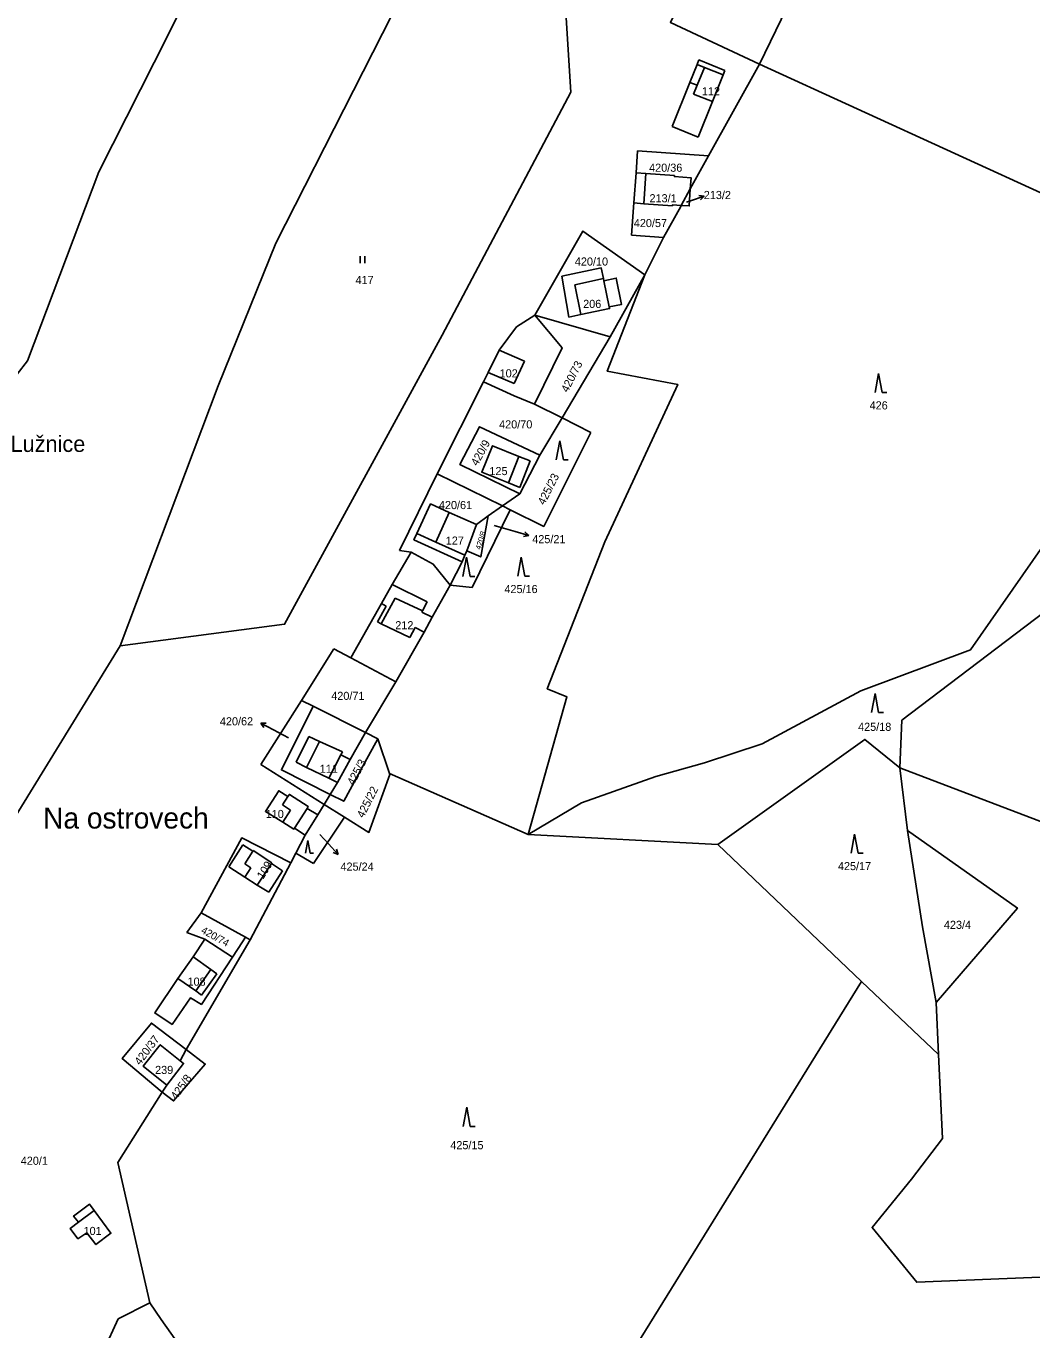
# Model space of a CAD drawing. Extents: x -7483133 to -743907, y -11317770 to -1129777.
# Drawn here: x -748843.6 to -748633, y -1130396.9 to -1130123.8 of the extents above; entities that cross this region are included whole.
import ezdxf

# ---------------------------------------------------------------- set-up
doc = ezdxf.new("R2010")
doc.units = 0
for name, color, linetype in [('Hranice parcel', 7, 'Continuous'), ('Parcelní čísla', 7, 'Continuous'), ('Pop  PČ popisy', 7, 'Continuous'), ('Vnitřní kresba', 7, 'Continuous'), ('Značky kultur', 7, 'Continuous')]:
    doc.layers.add(name, color=color, linetype=linetype)

msp = doc.modelspace()

# ---------------------------------------------------------------- linework, layer by layer
at = {"layer": 'Hranice parcel'}
for p, q in [((-748679.01, -1130109.09), (-748690.03, -1130131.77)), ((-748697.25, -1130133.11), (-748702.73, -1130130.9)), ((-748700.69, -1130150.98), (-748690.03, -1130131.77)), ((-748708.33, -1130144.85), (-748702.84, -1130147.05)), ((-748704.51, -1130157.91), (-748700.69, -1130150.98)), ((-748716.32, -1130160.85), (-748715.86, -1130154.54)), ((-748706.41, -1130161.37), (-748704.51, -1130157.91)), ((-748714, -1130175.92), (-748710.11, -1130168.08)), ((-748721.25, -1130188.87), (-748714, -1130175.92)), ((-748737.09, -1130184.36), (-748721.25, -1130188.87)), ((-748721.25, -1130188.87), (-748731.36, -1130205.88)), ((-748757.48, -1130217.6), (-748747.82, -1130198.29)), ((-748731.36, -1130205.88), (-748737.1, -1130203.01)), ((-748735.98, -1130213.67), (-748731.36, -1130205.88)), ((-748731.36, -1130205.88), (-748725.34, -1130208.89)), ((-748740.17, -1130221.76), (-748735.98, -1130213.67)), ((-748740.23, -1130220.41), (-748738.01, -1130214.88)), ((-748765.43, -1130233.66), (-748757.48, -1130217.6)), ((-748743.82, -1130224.3), (-748757.48, -1130217.6)), ((-748743.82, -1130224.3), (-748740.17, -1130221.76)), ((-748746.82, -1130226.39), (-748743.82, -1130224.3)), ((-748742.19, -1130225.1), (-748743.82, -1130224.3)), ((-748742.19, -1130225.1), (-748750.19, -1130241.4)), ((-748746.82, -1130226.39), (-748749.28, -1130228.17)), ((-748751.33, -1130233.71), (-748749.28, -1130228.17)), ((-748762.98, -1130234.01), (-748765.43, -1130233.66)), ((-748754.82, -1130240.9), (-748752.26, -1130236.01)), ((-748750.19, -1130241.4), (-748754.82, -1130240.9)), ((-748785.95, -1130265.03), (-748779.14, -1130254.21)), ((-748779.14, -1130254.21), (-748775.58, -1130256.1)), ((-748775.58, -1130256.1), (-748766.14, -1130261.11)), ((-748766.14, -1130261.11), (-748772.5, -1130271.71)), ((-748794.41, -1130278.46), (-748785.95, -1130265.03)), ((-748783.49, -1130266.25), (-748785.95, -1130265.03)), ((-748772.5, -1130271.71), (-748783.49, -1130266.25)), ((-748769.96, -1130273.07), (-748772.5, -1130271.71)), ((-748769.96, -1130273.07), (-748767.48, -1130280.32)), ((-748781.17, -1130286.79), (-748794.41, -1130278.46)), ((-748660.62, -1130279.14), (-748659.01, -1130292.27)), ((-748738.44, -1130293.13), (-748767.48, -1130280.32)), ((-748767.48, -1130280.32), (-748767.41, -1130280.54)), ((-748781.17, -1130286.79), (-748779.93, -1130284.72)), ((-748782.51, -1130289.02), (-748781.17, -1130286.79)), ((-748781.17, -1130286.79), (-748776.93, -1130289.46)), ((-748785.13, -1130293.23), (-748782.51, -1130289.02)), ((-748776.93, -1130289.46), (-748783.4, -1130299.2)), ((-748787.12, -1130297.03), (-748785.13, -1130293.23)), ((-748698.75, -1130295.21), (-748738.44, -1130293.13)), ((-748668.63, -1130323.88), (-748698.75, -1130295.21)), ((-748788.18, -1130299.06), (-748787.12, -1130297.03)), ((-748783.4, -1130299.2), (-748787.12, -1130297.03)), ((-748796.64, -1130315.17), (-748788.18, -1130299.06)), ((-748809.94, -1130313.62), (-748806.96, -1130309.5)), ((-748806.96, -1130309.5), (-748797.65, -1130314.62)), ((-748806.14, -1130315.03), (-748809.94, -1130313.62)), ((-748800.38, -1130318.82), (-748806.14, -1130315.03)), ((-748797.65, -1130314.62), (-748796.64, -1130315.17)), ((-748810.09, -1130338.15), (-748796.64, -1130315.17)), ((-748652.52, -1130339.21), (-748668.63, -1130323.88)), ((-748653.04, -1130328.3), (-748652.52, -1130339.21)), ((-748811.31, -1130340.5), (-748810.09, -1130338.15)), ((-748815.11, -1130347.07), (-748814.15, -1130345.6))]:
    msp.add_line(p, q, dxfattribs=at)
for points in [[(-748769.65, -1130027.77), (-748783.5, -1130064.22), (-748813.85, -1130125.61), (-748828.39, -1130154.34), (-748843.29, -1130193.93), (-748849.85, -1130202.28), (-748880.72, -1130244.6), (-748895.14, -1130258.31), (-748902.53, -1130266.04), (-748946.04, -1130295.61), (-748968.51, -1130326.73), (-748986.86, -1130352.14), (-749004.75, -1130374.8), (-749024.24, -1130390.9), (-749046.5, -1130403.57), (-749076.25, -1130410.73)], [(-748690.03, -1130131.77), (-748708.67, -1130123.04), (-748703.2, -1130111.36), (-748695.73, -1130100.54)], [(-748758.78, -1130105.24), (-748791.3, -1130169.26), (-748803.39, -1130199.17), (-748823.92, -1130253.6)], [(-748823.92, -1130253.6), (-748789.46, -1130249.07), (-748756.47, -1130188.54), (-748729.51, -1130137.61), (-748730.72, -1130118.71)], [(-748702.73, -1130130.9), (-748703.1, -1130131.83), (-748704.61, -1130135.59), (-748708.33, -1130144.85)], [(-748690.03, -1130131.77), (-748628.64, -1130159.81), (-748623.71, -1130149.3)], [(-748702.84, -1130147.05), (-748699.88, -1130139.6), (-748697.62, -1130134.04), (-748697.25, -1130133.11)], [(-748715.86, -1130154.54), (-748715.53, -1130149.95), (-748700.69, -1130150.98)], [(-748715.86, -1130154.54), (-748713.83, -1130154.69), (-748707.83, -1130155.12), (-748707.84, -1130155.32), (-748704.35, -1130155.56), (-748704.51, -1130157.91)], [(-748704.51, -1130157.91), (-748704.74, -1130161.48), (-748706.41, -1130161.37)], [(-748710.11, -1130168.08), (-748716.81, -1130167.59), (-748716.32, -1130160.85)], [(-748706.41, -1130161.37), (-748708.24, -1130161.24), (-748708.25, -1130161.44), (-748714.25, -1130161), (-748716.32, -1130160.85)], [(-748710.11, -1130168.08), (-748706.52, -1130161.56), (-748706.41, -1130161.37)], [(-748737.09, -1130184.36), (-748726.98, -1130166.73), (-748714, -1130175.92)], [(-748731.39, -1130176.15), (-748729.92, -1130184.74), (-748727.41, -1130184.22), (-748721.4, -1130182.98), (-748721.47, -1130182.61), (-748718.88, -1130182.08), (-748720.01, -1130176.57), (-748722.61, -1130177.15), (-748722.7, -1130176.69), (-748723.16, -1130174.45), (-748731.39, -1130176.15)], [(-748738.44, -1130293.13), (-748730.34, -1130264.28), (-748734.46, -1130262.58), (-748722.39, -1130231.8), (-748707.13, -1130198.83), (-748721.89, -1130196.08), (-748714, -1130175.92)], [(-748737.09, -1130184.36), (-748740.9, -1130186.8), (-748744.52, -1130191.64), (-748746.84, -1130196.34), (-748747.82, -1130198.29)], [(-748737.1, -1130203.01), (-748731.34, -1130191.16), (-748737.09, -1130184.36)], [(-748747.82, -1130198.29), (-748741.36, -1130201.22), (-748737.1, -1130203.01)], [(-748735.98, -1130213.67), (-748748.65, -1130207.73), (-748752.73, -1130215.64), (-748740.17, -1130221.76)], [(-748725.34, -1130208.89), (-748735.2, -1130228.6), (-748742.19, -1130225.1)], [(-748738.01, -1130214.88), (-748740.38, -1130213.93), (-748745.94, -1130211.69), (-748748.16, -1130217.21), (-748742.6, -1130219.46), (-748740.23, -1130220.41)], [(-748749.28, -1130228.17), (-748754.98, -1130225.64), (-748758.89, -1130223.86), (-748761.74, -1130230.08), (-748762.39, -1130231.38), (-748752.26, -1130236.01)], [(-748751.33, -1130233.71), (-748748.4, -1130234.96), (-748746.82, -1130226.39)], [(-748619.86, -1130238.05), (-748630.7, -1130232.75), (-748645.83, -1130254.45), (-748668.82, -1130263), (-748689.45, -1130274.13), (-748701.54, -1130278.1), (-748711.73, -1130280.94), (-748727.3, -1130286.44), (-748738.44, -1130293.13)], [(-748762.98, -1130234.01), (-748766.91, -1130240.77), (-748769.14, -1130244.76), (-748775.58, -1130256.1)], [(-748754.82, -1130240.9), (-748758.32, -1130236.48), (-748762.98, -1130234.01)], [(-748752.26, -1130236.01), (-748751.69, -1130234.6), (-748751.33, -1130233.71)], [(-748766.14, -1130261.11), (-748760.24, -1130250.76), (-748758.55, -1130247.6), (-748754.82, -1130240.9)], [(-748602.94, -1130272.05), (-748603.83, -1130270.75), (-748594.68, -1130253.65), (-748610.6, -1130247.49), (-748624.3, -1130241.91), (-748660.24, -1130269.18), (-748660.62, -1130279.14)], [(-748823.92, -1130253.6), (-748854.96, -1130304.08), (-748855.51, -1130336.17), (-748864.43, -1130348.37)], [(-748783.49, -1130266.25), (-748790.13, -1130279.57), (-748779.93, -1130284.72)], [(-748779.93, -1130284.72), (-748778.37, -1130282.24), (-748775.74, -1130277.43), (-748772.5, -1130271.71)], [(-748779.93, -1130284.72), (-748777.08, -1130286.16), (-748772.66, -1130278.04), (-748769.96, -1130273.07)], [(-748660.62, -1130279.14), (-748667.98, -1130273.2), (-748698.75, -1130295.21)], [(-748599.78, -1130276.68), (-748625.99, -1130292.35), (-748660.62, -1130279.14)], [(-748767.41, -1130280.54), (-748771.8, -1130292.68), (-748776.93, -1130289.46)], [(-748782.51, -1130289.02), (-748784.73, -1130287.64), (-748784.5, -1130287.26), (-748788.46, -1130284.72), (-748788.75, -1130285.18), (-748790.68, -1130283.93), (-748793.48, -1130288.27), (-748789.82, -1130290.55), (-748787.52, -1130291.98), (-748787.42, -1130291.81), (-748785.13, -1130293.23)], [(-748659.01, -1130292.27), (-748635.99, -1130308.5), (-748653.04, -1130328.3)], [(-748659.01, -1130292.27), (-748655.88, -1130312.42), (-748653.04, -1130328.3)], [(-748788.18, -1130299.06), (-748798.43, -1130293.81), (-748806.96, -1130309.5)], [(-748806.14, -1130315.03), (-748808.63, -1130318.75), (-748811.81, -1130323.23), (-748816.64, -1130330.48), (-748813.01, -1130332.88), (-748809.18, -1130327.32), (-748806.88, -1130328.7), (-748800.38, -1130318.82)], [(-748797.65, -1130314.62), (-748798.26, -1130315.56), (-748800.38, -1130318.82)], [(-748668.63, -1130323.88), (-748723.49, -1130412.55), (-748757.6, -1130467.05)], [(-748815.11, -1130347.07), (-748823.47, -1130340.04), (-748817.34, -1130332.61), (-748810.09, -1130338.15)], [(-748811.31, -1130340.5), (-748815.51, -1130337.13), (-748819.07, -1130341.63), (-748814.15, -1130345.6)], [(-748815.11, -1130347.07), (-748812.71, -1130348.9), (-748806.07, -1130341.2), (-748810.09, -1130338.15)], [(-748652.52, -1130339.21), (-748651.69, -1130356.8), (-748658.21, -1130365.26), (-748666.43, -1130375.43), (-748657.09, -1130386.87), (-748627.84, -1130385.7), (-748608.98, -1130393.62)], [(-748814.15, -1130345.6), (-748810.6, -1130341.06), (-748811.31, -1130340.5)], [(-748817.71, -1130391.16), (-748824.37, -1130361.8), (-748815.11, -1130347.07)], [(-748830.87, -1130376.52), (-748828.98, -1130378.98), (-748825.82, -1130376.61), (-748829.31, -1130371.87), (-748830.3, -1130370.53), (-748833.64, -1130373.02), (-748832.62, -1130374.32), (-748834.33, -1130375.61), (-748832.74, -1130377.75), (-748830.87, -1130376.52)], [(-748825.64, -1130435.7), (-748830.6, -1130413.85), (-748827.29, -1130401.09), (-748824.29, -1130394.55), (-748817.71, -1130391.16)], [(-748804.37, -1130410.14), (-748815.28, -1130394.69), (-748817.71, -1130391.16)]]:
    msp.add_lwpolyline(points, dxfattribs=at)
at = {"layer": 'Pop  PČ popisy'}
for p, q in [((-748704.43, -1130160.38), (-748701.59, -1130159.4)), ((-748701.59, -1130159.4), (-748702.7, -1130159.26)), ((-748701.59, -1130159.4), (-748702.38, -1130160.2)), ((-748705.32, -1130160.69), (-748704.43, -1130160.38)), ((-748745.61, -1130228.38), (-748741.21, -1130229.65)), ((-748741.21, -1130229.65), (-748738.33, -1130230.48)), ((-748738.33, -1130230.48), (-748739.43, -1130230.68)), ((-748738.33, -1130230.48), (-748739.15, -1130229.72)), ((-748791.8, -1130271.18), (-748794.45, -1130269.77)), ((-748794.45, -1130269.77), (-748793.33, -1130269.8)), ((-748794.45, -1130269.77), (-748793.8, -1130270.68)), ((-748788.66, -1130272.87), (-748791.8, -1130271.18)), ((-748782.11, -1130293.1), (-748780.3, -1130295.07)), ((-748780.3, -1130295.07), (-748778.25, -1130297.27)), ((-748778.25, -1130297.27), (-748779.3, -1130296.87)), ((-748778.25, -1130297.27), (-748778.57, -1130296.19))]:
    msp.add_line(p, q, dxfattribs=at)
at = {"layer": 'Vnitřní kresba'}
for p, q in [((-748701.56, -1130132.45), (-748703.1, -1130131.83)), ((-748701.56, -1130132.45), (-748703.07, -1130136.19)), ((-748697.62, -1130134.04), (-748701.56, -1130132.45)), ((-748703.07, -1130136.19), (-748704.61, -1130135.59)), ((-748703.81, -1130138.03), (-748703.07, -1130136.19)), ((-748699.88, -1130139.6), (-748703.81, -1130138.03)), ((-748713.83, -1130154.69), (-748714.25, -1130161)), ((-748728.7, -1130178), (-748722.7, -1130176.69)), ((-748728.7, -1130178), (-748727.41, -1130184.22)), ((-748722.61, -1130177.15), (-748721.47, -1130182.61)), ((-748744.52, -1130191.64), (-748739.2, -1130193.97)), ((-748739.2, -1130193.97), (-748741.36, -1130198.67)), ((-748741.36, -1130198.67), (-748746.84, -1130196.34)), ((-748740.38, -1130213.93), (-748742.6, -1130219.46)), ((-748754.98, -1130225.64), (-748757.76, -1130231.87)), ((-748761.74, -1130230.08), (-748757.76, -1130231.87)), ((-748757.76, -1130231.87), (-748751.69, -1130234.6)), ((-748766.91, -1130240.77), (-748759.59, -1130244.35)), ((-748769.23, -1130249), (-748766.3, -1130243.62)), ((-748760.57, -1130246.28), (-748766.3, -1130243.62)), ((-748769.98, -1130248.6), (-748768.19, -1130245.29)), ((-748768.19, -1130245.29), (-748769.14, -1130244.76)), ((-748760.57, -1130246.28), (-748760.7, -1130246.53)), ((-748760.7, -1130246.53), (-748758.55, -1130247.6)), ((-748759.59, -1130244.35), (-748760.57, -1130246.28)), ((-748769.23, -1130249), (-748769.98, -1130248.6)), ((-748769.23, -1130249), (-748763.24, -1130251.82)), ((-748763.24, -1130251.82), (-748762.13, -1130249.77)), ((-748762.13, -1130249.77), (-748760.24, -1130250.76)), ((-748784.36, -1130272.57), (-748787.03, -1130277.99)), ((-748782.13, -1130273.6), (-748784.84, -1130279.06)), ((-748784.36, -1130272.57), (-748782.13, -1130273.6)), ((-748782.13, -1130273.6), (-748777.35, -1130275.8)), ((-748777.66, -1130276.43), (-748780.2, -1130281.31)), ((-748777.35, -1130275.8), (-748777.66, -1130276.43)), ((-748777.66, -1130276.43), (-748775.74, -1130277.43)), ((-748787.03, -1130277.99), (-748784.84, -1130279.06)), ((-748784.84, -1130279.06), (-748780.2, -1130281.31)), ((-748780.2, -1130281.31), (-748778.37, -1130282.24)), ((-748789.9, -1130286.91), (-748788.75, -1130285.18)), ((-748788.2, -1130288.01), (-748789.9, -1130286.91)), ((-748784.73, -1130287.64), (-748787.42, -1130291.81)), ((-748788.2, -1130288.01), (-748789.82, -1130290.55)), ((-748801.13, -1130299.89), (-748798.19, -1130295.26)), ((-748798.19, -1130295.26), (-748796.14, -1130296.6)), ((-748797.81, -1130299.24), (-748796.14, -1130296.6)), ((-748796.14, -1130296.6), (-748796.06, -1130296.47)), ((-748796.06, -1130296.47), (-748792.1, -1130299.05)), ((-748801.13, -1130299.89), (-748797.8, -1130302.06)), ((-748796.51, -1130300.08), (-748797.81, -1130299.24)), ((-748796.51, -1130300.08), (-748797.8, -1130302.06)), ((-748792.21, -1130299.21), (-748795.2, -1130303.75)), ((-748789.87, -1130300.75), (-748792.77, -1130305.21)), ((-748792.1, -1130299.05), (-748792.21, -1130299.21)), ((-748792.21, -1130299.21), (-748789.87, -1130300.75)), ((-748797.8, -1130302.06), (-748795.2, -1130303.75)), ((-748792.77, -1130305.21), (-748795.2, -1130303.75)), ((-748808.63, -1130318.75), (-748804.89, -1130321.4)), ((-748808.08, -1130325.85), (-748811.81, -1130323.23)), ((-748804.89, -1130321.4), (-748808.08, -1130325.85)), ((-748803.64, -1130322.29), (-748806.86, -1130326.76)), ((-748804.89, -1130321.4), (-748803.64, -1130322.29)), ((-748806.86, -1130326.76), (-748808.08, -1130325.85)), ((-748832.62, -1130374.32), (-748829.31, -1130371.87))]:
    msp.add_line(p, q, dxfattribs=at)
at = {"layer": 'Značky kultur'}
for p, q in [((-748773.65, -1130173.46), (-748773.65, -1130171.96)), ((-748772.65, -1130173.46), (-748772.65, -1130171.96)), ((-748665.07, -1130196.54), (-748665.82, -1130200.54)), ((-748664.32, -1130200.54), (-748665.07, -1130196.54)), ((-748664.32, -1130200.54), (-748663.32, -1130200.54)), ((-748731.82, -1130210.65), (-748732.57, -1130214.65)), ((-748731.07, -1130214.65), (-748731.82, -1130210.65)), ((-748731.07, -1130214.65), (-748730.07, -1130214.65)), ((-748751.37, -1130235.05), (-748752.12, -1130239.05)), ((-748750.62, -1130239.05), (-748751.37, -1130235.05)), ((-748739.9, -1130235), (-748740.65, -1130239)), ((-748739.15, -1130239), (-748739.9, -1130235)), ((-748750.62, -1130239.05), (-748749.62, -1130239.05)), ((-748739.15, -1130239), (-748738.15, -1130239)), ((-748665.82, -1130263.59), (-748666.57, -1130267.59)), ((-748665.07, -1130267.59), (-748665.82, -1130263.59)), ((-748665.07, -1130267.59), (-748664.07, -1130267.59)), ((-748670.09, -1130293.02), (-748670.84, -1130297.02)), ((-748669.34, -1130297.02), (-748670.09, -1130293.02)), ((-748784.58, -1130294.37), (-748785.08, -1130297.05)), ((-748784.08, -1130297.05), (-748784.58, -1130294.37)), ((-748784.08, -1130297.05), (-748783.41, -1130297.05)), ((-748669.34, -1130297.02), (-748668.34, -1130297.02)), ((-748751.33, -1130350.23), (-748752.08, -1130354.23)), ((-748750.58, -1130354.23), (-748751.33, -1130350.23)), ((-748750.58, -1130354.23), (-748749.58, -1130354.23))]:
    msp.add_line(p, q, dxfattribs=at)

# ---------------------------------------------------------------- texts
at = {"layer": 'Parcelní čísla'}
for s, p in [('112', (-748702.07, -1130138.31)), ('420/36', (-748713.13, -1130154.31)), ('213/1', (-748713.05, -1130160.71)), ('213/2', (-748701.68, -1130160.03)), ('420/57', (-748716.33, -1130165.9)), ('420/10', (-748728.68, -1130173.96)), ('417', (-748774.61, -1130177.83)), ('206', (-748726.94, -1130182.83)), ('102', (-748744.43, -1130197.38)), ('426', (-748666.96, -1130204.09)), ('420/70', (-748744.54, -1130208.06)), ('125', (-748746.57, -1130217.84)), ('420/61', (-748757.15, -1130224.96)), ('425/21', (-748737.6, -1130232.1)), ('127', (-748755.71, -1130232.41)), ('425/16', (-748743.43, -1130242.55)), ('212', (-748766.28, -1130250.13)), ('420/71', (-748779.69, -1130264.92)), ('420/62', (-748803.01, -1130270.25)), ('425/18', (-748669.37, -1130271.4)), ('111', (-748782.1, -1130280.19)), ('110', (-748793.42, -1130289.66)), ('425/24', (-748777.76, -1130300.68)), ('425/17', (-748673.59, -1130300.57)), ('423/4', (-748651.4, -1130312.87)), ('108', (-748809.79, -1130324.77)), ('239', (-748816.58, -1130343.26)), ('425/15', (-748754.76, -1130359.02)), ('420/1', (-748844.71, -1130362.28)), ('101', (-748831.56, -1130376.98))]:
    msp.add_text(s, height=1.7, dxfattribs=at).set_placement(p)
for s, height, rotation, p in [('420/73', 1.7, 63, (-748730.17, -1130200.67)), ('420/9', 1.7, 61, (-748749.09, -1130216.04)), ('425/23', 1.7, 63, (-748735.06, -1130224.23)), ('420/8', 1.14, 73, (-748748.45, -1130233.55)), ('425/3', 1.7, 62, (-748774.98, -1130282.95)), ('425/22', 1.7, 63, (-748772.94, -1130289.78)), ('109', 1.7, 58, (-748793.96, -1130302.59)), ('420/74', 1.535, 331, (-748807.1, -1130313.62)), ('420/37', 1.7, 53, (-748819.72, -1130341.55)), ('425/8', 1.7, 55, (-748812.08, -1130348.77))]:
    msp.add_text(s, height=height, rotation=rotation, dxfattribs=at).set_placement(p)
at = {"layer": 'Pop  PČ popisy'}
for s, height, p in [('Lužnice', 3.4, (-748846.86, -1130212.99)), ('Na ostrovech', 4.4, (-748840.02, -1130291.86))]:
    msp.add_text(s, height=height, dxfattribs=at).set_placement(p)

doc.saveas('drawing.dxf')
